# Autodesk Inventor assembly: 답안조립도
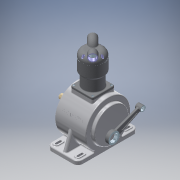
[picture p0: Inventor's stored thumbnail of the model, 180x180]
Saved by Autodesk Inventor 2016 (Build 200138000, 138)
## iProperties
Created: 2015-06
Part Number: 답안조립도
Document SubType Name: Assembly
Designer: Administrator
Author: Administrator
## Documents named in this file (9)
- C:\Users\Administrator\Desktop\450606V1013\답안조립도.iam
- C:\Users\Administrator\Desktop\450606V1013\본체.ipt
- C:\Users\Administrator\Desktop\450606V1013\실린더.ipt
- C:\Users\Administrator\Desktop\450606V1013\실린더헤드.ipt
- C:\Users\Administrator\Desktop\450606V1013\메인커버.ipt
- C:\Users\Administrator\Desktop\450606V1013\메인 크랭크 축-구동부.ipt
- C:\Users\Administrator\Desktop\450606V1013\베어링 6204.ipt
- C:\Users\Administrator\Desktop\450606V1013\크랭크 서브축.ipt
- C:\Users\Administrator\Desktop\450606V1013\커넥팅 로드.ipt
